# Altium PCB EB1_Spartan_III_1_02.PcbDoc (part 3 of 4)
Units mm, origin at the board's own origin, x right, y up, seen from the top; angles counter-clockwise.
Board outline 165.1 x 115.01 mm, 6 copper layers (Top Layer, MidLayer1, VCC Plane, GND Plane, MidLayer2, Bottom Layer); 356 components, 386 nets, 1788 pads, 779 vias.
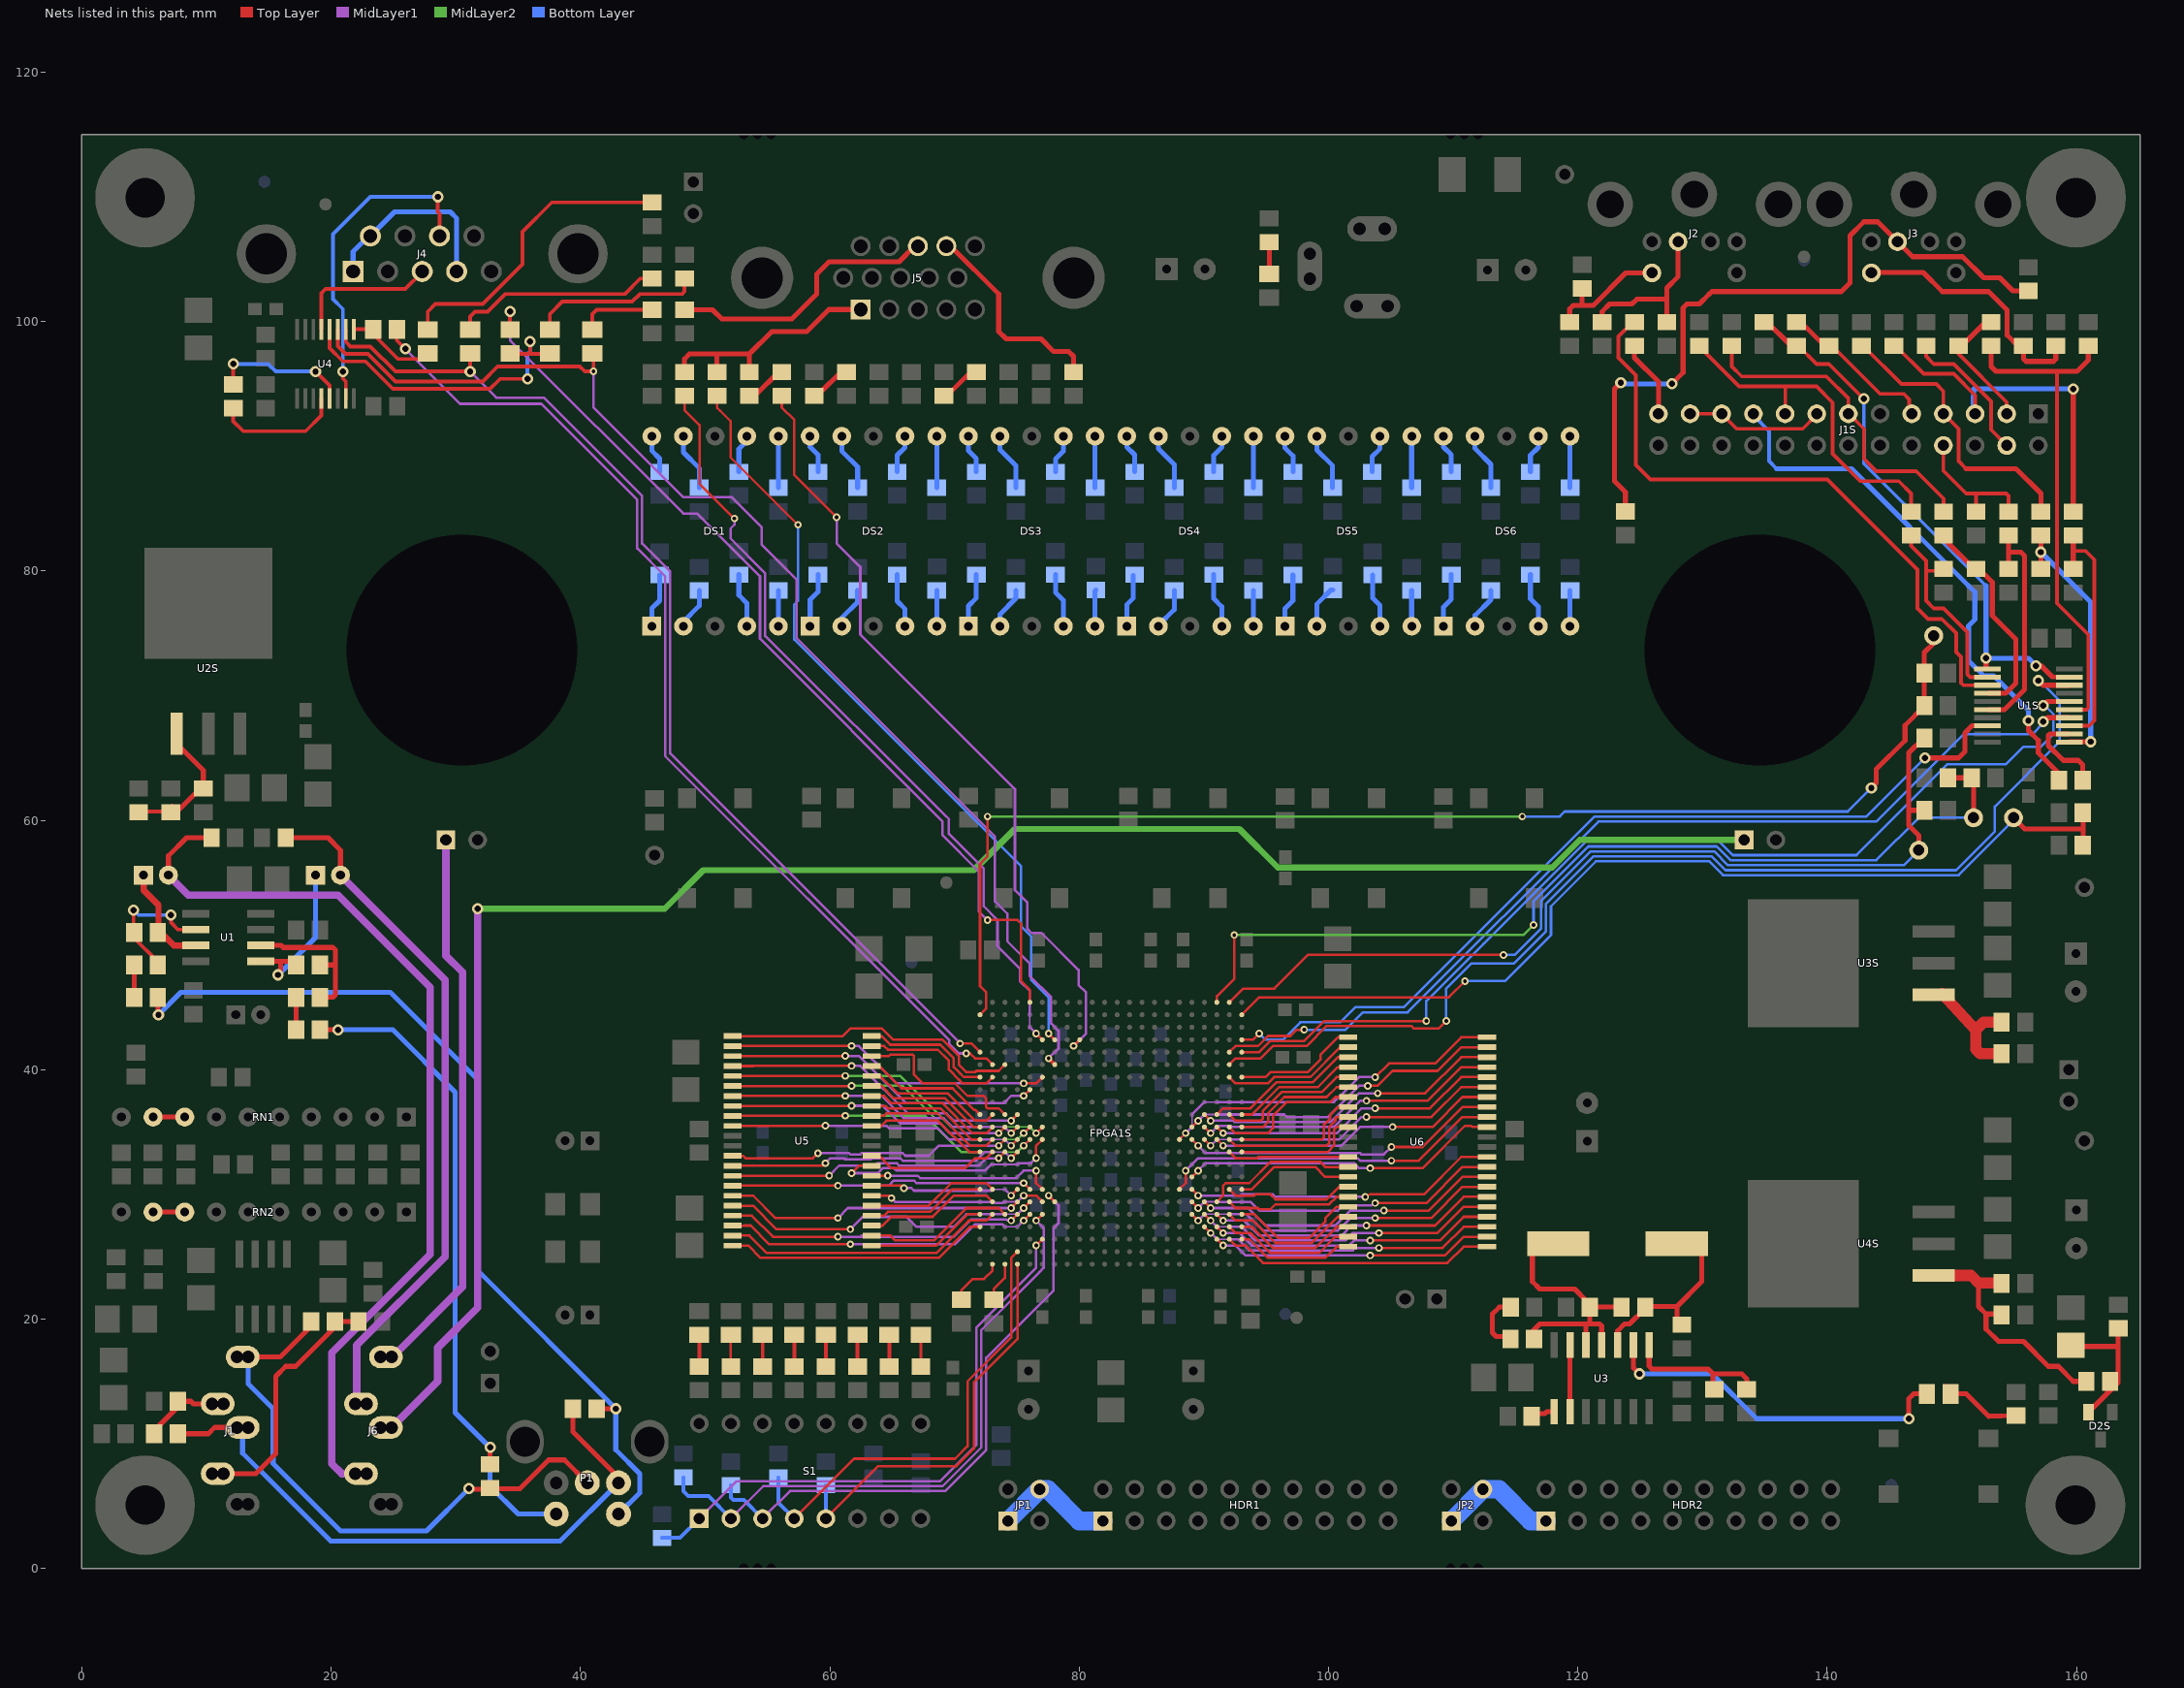
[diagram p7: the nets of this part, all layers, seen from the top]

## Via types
v1: diameter 0.6, hole 0.3, Top Layer to Bottom Layer, tented both sides, 427 vias
v2: diameter 1.6, hole 1, Top Layer to Bottom Layer, 224 vias
v3: diameter 0.9, hole 0.5, Top Layer to Bottom Layer, tented both sides, 126 vias
v4: diameter 1.27, hole 0.711, Top Layer to Bottom Layer, tented both sides, 2 vias

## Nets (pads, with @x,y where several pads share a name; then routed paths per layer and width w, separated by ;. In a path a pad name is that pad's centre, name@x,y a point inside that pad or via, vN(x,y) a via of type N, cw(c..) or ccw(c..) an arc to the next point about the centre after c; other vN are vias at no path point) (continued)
NetC22_1: C22.1 U4.4 | length 10.3
  Top Layer w0.3: C22.1@12.15,93.05 12.15,92 12.95,91.2 17.95,91.2 19.225,92.475 U4.4@19.225,93.825
NetC22_2: C22.2 U4.5 | length 11.1
  Top Layer w0.3: C22.2@12.15,94.95 v3(12.15,96.6) ; v3(18.75,96) 19.875,94.875 U4.5@19.875,93.825
  Bottom Layer w0.3: v3(12.15,96.6) 14.95,96.6 15.55,96 v3(18.75,96)
NetC30_2: C30.2 L1.2 | length 4.9
  Top Layer w0.4: C30.2@114.62,20.955 113.705,20.955 113.15,20.4 113.15,18.9 113.45,18.6 114.6,18.6 L1.2@114.7,18.6
NetC31_1: C31.1 CR1.2 R112.2 U3.3 | length 15.3
  Top Layer w0.4: U3.3@123.19,17.915 123.19,19.04 123.75,19.6 124.15,19.6 R112.2@125.35,20.8 ; R112.2@125.35,21 125.355,21.005 125.41,21.005 127.955,21.005 ; CR1.2@127.94,26.035 129.515,26.035 129.95,25.6 129.95,23 127.955,21.005 ; C31.1@127.95,19.9 127.955,19.905 127.955,21.005
NetC32_2: C32.2 CR1.1 L1.1 R112.1 U3.4 U3.5 | length 23.5
  Top Layer w0.4: L1.1@116.42,18.6 116.42,19.07 116.95,19.6 120.55,19.6 ; CR1.1@118.35,26 116.35,26 116.35,23 116.95,22.4 119.75,22.4 C32.2@120.75,21.4 ; U3.5@120.65,17.915 120.65,19.5 120.55,19.6 ; C32.2@120.95,21 120.95,20.955 120.95,19.6 ; C32.2@120.965,20.955 R112.1@123.51,20.955 ; U3.4@121.92,17.915 121.92,19.43 121.75,19.6 120.95,19.6 ; 120.55,19.6 120.95,19.6
NetC33_1: C33.1 P1.2 R115.2 | length 53.3
  Top Layer w0.4: C33.1@19.1,43.2 v3(20.55,43.2) ; R115.2@32.75,8.3 R115.2@32.75,8.35 v3(32.75,9.7)
  Bottom Layer w0.4: v3(20.55,43.2) 24.95,43.2 29.95,38.2 29.95,12.5 v3(32.75,9.7) 32.75,6.6 34.99,4.36 P1.2@38.05,4.36
NetC33_2: C33.2 R116.1 | length 2.6
  Top Layer w0.4: C33.2@17.2,43.2 R116.1@17.2,45.8
NetC35_1: C35.1 P1.5 R114.2 | length 73.1
  Top Layer w0.4: C35.1@6.1,45.8 6.1,44.45 v3(6.15,44.4) ; R114.2@41.3,12.8 v3(42.85,12.8)
  Bottom Layer w0.4: v3(6.15,44.4) 7.95,46.2 24.75,46.2 31.75,39.2 31.75,23.9 42.84,12.81 42.84,12.8 42.84,9.51 44.75,7.6 44.75,6.06 P1.5@43.05,4.36
NetC35_2: C35.2 R117.1 | length 2.6
  Top Layer w0.4: C35.2@4.2,45.8 R117.1@4.2,48.4
NetC36_1: C36.1 R118.2 U1.1 | length 13.5
  Top Layer w0.4: U1.1@14.35,48.695 15.95,48.695 ; v3(15.75,47.6) 15.95,47.8 15.95,48.695 ; R118.2@17.35,48.6 17.255,48.695 17.2,48.695 15.95,48.695
  Bottom Layer w0.4: v3(15.75,47.6) 18.75,50.6 C36.1@18.75,55.6
NetC36_2: C36.2 J6.4 J6.4A J6.4B R120.2 | length 56.7
  Top Layer w0.4: R120.2@16.35,58.6 19.75,58.6 20.75,57.6 C36.2@20.75,55.6
  MidLayer1 w0.6: C36.2@20.75,55.6 29.15,47.2 29.15,25 22.05,17.9 22.05,13.3 J6.4B@22.15,13.2 ; J6.4B@21.95,13.2 J6.4B@22.15,13.2 ; J6.4A@22.75,13.3 J6.4A@22.65,13.2 ; J6.4A@22.85,13.2 J6.4A@22.65,13.2 ; J6.4B@22.15,13.2 J6.4@22.4,13.2 J6.4A@22.65,13.2
NetC38_1: C38.1 R119.2 U1.7 | length 8.4
  Top Layer w0.5: C38.1@4.95,55.6 4.95,54.4 6.15,53.2 6.15,51.2 6.225,51.125 7.385,49.965 U1.7@9.15,49.965
NetC38_2: C38.2 J6.2 J6.2A J6.2B R121.2 | length 74.9
  Top Layer w0.4: C38.2@6.95,55.6 6.95,57.15 8.4,58.6 R121.2@10.4,58.6
  MidLayer1 w0.6: C38.2@6.95,55.6 8.55,54 20.55,54 27.95,46.6 27.95,25.2 20.05,17.3 20.05,8.4 20.85,7.6 J6.2B@21.95,7.6 J6.2@22.4,7.6 J6.2A@22.85,7.6
NetC79S_2: C79S.2 D2S.2 R30S.1 R38S.2 | length 12.1
  Top Layer w0.4: C79S.2@159.95,17.8 163.35,17.8 ; D2S.2@160.975,12.53 163.073,14.627 163.35,14.905 163.35,15 163.35,17.8 ; R30S.1@163.35,19.25 163.35,17.8
  Top Layer w0.5: 162.55,14.2 163.025,14.675 163.05,14.7 R38S.2@163.05,15
NetDS1_1: DS1.1 R41.1 | length 4.4
  Bottom Layer w0.4: DS1.1@45.72,75.565 45.72,76.99 46.35,77.62 R41.1@46.35,79.67
NetDS1_2: DS1.2 R37.1 | length 3.4
  Bottom Layer w0.4: DS1.2@48.26,75.565 48.26,75.93 49.53,77.2 R37.1@49.53,78.425
NetDS1_4: DS1.4 R33.1 | length 4.4
  Bottom Layer w0.4: R33.1@52.705,79.695 52.705,78.065 53.34,77.43 DS1.4@53.34,75.565
NetDS1_5: DS1.5 R53.1 | length 2.9
  Bottom Layer w0.4: DS1.5@55.88,75.565 R53.1@55.88,78.425
NetDS1_6: DS1.6 R29.1 | length 4.1
  Bottom Layer w0.4: R29.1@55.88,86.675 DS1.6@55.88,90.805
NetDS1_7: DS1.7 R25.1 | length 3.1
  Bottom Layer w0.4: R25.1@52.705,87.945 52.705,89.775 53.34,90.41 DS1.7@53.34,90.805
NetDS1_9: DS1.9 R45.1 | length 4.7
  Bottom Layer w0.4: DS1.9@48.26,90.805 48.26,89.51 49.53,88.24 R45.1@49.53,86.675
NetDS1_10: DS1.10 R49.1 | length 3.1
  Bottom Layer w0.4: DS1.10@45.72,90.805 45.72,89.65 46.355,89.015 R49.1@46.355,87.945
NetDS2_1: DS2.1 R42.1 | length 4.4
  Bottom Layer w0.4: DS2.1@58.42,75.565 58.42,77.69 59.055,78.325 R42.1@59.055,79.695
NetDS2_2: DS2.2 R38.1 | length 3.4
  Bottom Layer w0.4: DS2.2@60.96,75.565 60.96,76.23 62.23,77.5 R38.1@62.23,78.425
NetDS2_4: DS2.4 R34.1 | length 4.4
  Bottom Layer w0.4: R34.1@65.405,79.695 65.405,77.565 66.04,76.93 DS2.4@66.04,75.565
NetDS2_5: DS2.5 R54.1 | length 2.9
  Bottom Layer w0.4: DS2.5@68.58,75.565 R54.1@68.58,78.425
NetDS2_6: DS2.6 R30.1 | length 4.1
  Bottom Layer w0.4: R30.1@68.58,86.675 DS2.6@68.58,90.805
NetDS2_7: DS2.7 R26.1 | length 3.1
  Bottom Layer w0.4: R26.1@65.405,87.945 65.405,89.275 66.04,89.91 DS2.7@66.04,90.805
NetDS2_9: DS2.9 R46.1 | length 4.7
  Bottom Layer w0.4: DS2.9@60.96,90.805 60.96,89.61 62.23,88.34 R46.1@62.23,86.675
NetDS2_10: DS2.10 R50.1 | length 3.1
  Bottom Layer w0.4: DS2.10@58.42,90.805 58.42,89.95 59.055,89.315 R50.1@59.055,87.945
NetDS3_1: DS3.1 R43.1 | length 4.4
  Bottom Layer w0.4: DS3.1@71.12,75.565 71.12,77.19 71.755,77.825 R43.1@71.755,79.695
NetDS3_2: DS3.2 R39.1 | length 3.4
  Bottom Layer w0.4: DS3.2@73.66,75.565 73.66,76.53 74.93,77.8 R39.1@74.93,78.425
NetDS3_4: DS3.4 R35.1 | length 4.4
  Bottom Layer w0.4: R35.1@78.105,79.695 78.105,78.265 78.74,77.63 DS3.4@78.74,75.565
NetDS3_5: DS3.5 R55.1 | length 2.9
  Bottom Layer w0.4: DS3.5@81.28,75.565 81.28,78.4 R55.1@81.35,78.47
NetDS3_6: DS3.6 R31.1 | length 4.1
  Bottom Layer w0.4: R31.1@81.28,86.675 DS3.6@81.28,90.805
NetDS3_7: DS3.7 R27.1 | length 3.1
  Bottom Layer w0.4: R27.1@78.105,87.945 78.105,88.975 78.74,89.61 DS3.7@78.74,90.805
NetDS3_9: DS3.9 R47.1 | length 4.7
  Bottom Layer w0.4: DS3.9@73.66,90.805 73.66,89.71 74.93,88.44 R47.1@74.93,86.675
NetDS3_10: DS3.10 R51.1 | length 3.1
  Bottom Layer w0.4: DS3.10@71.12,90.805 71.12,89.65 71.755,89.015 R51.1@71.755,87.945
NetDS4_1: DS4.1 R44.1 | length 4.3
  Bottom Layer w0.4: DS4.1@83.82,75.565 83.82,77.29 84.35,77.82 R44.1@84.35,79.62
NetDS4_2: DS4.2 R40.1 | length 3.4
  Bottom Layer w0.4: DS4.2@86.36,75.565 86.36,75.63 87.63,76.9 R40.1@87.63,78.425
NetDS4_4: DS4.4 R36.1 | length 4.4
  Bottom Layer w0.4: R36.1@90.805,79.695 90.805,77.765 91.44,77.13 DS4.4@91.44,75.565
NetDS4_5: DS4.5 R56.1 | length 2.9
  Bottom Layer w0.4: DS4.5@93.98,75.565 R56.1@93.98,78.425
NetDS4_6: DS4.6 R32.1 | length 4.1
  Bottom Layer w0.4: R32.1@93.98,86.675 DS4.6@93.98,90.805
NetDS4_7: DS4.7 R28.1 | length 3.1
  Bottom Layer w0.4: R28.1@90.805,87.945 90.805,89.275 91.44,89.91 DS4.7@91.44,90.805
NetDS4_9: DS4.9 R48.1 | length 4.7
  Bottom Layer w0.4: DS4.9@86.36,90.805 86.36,89.81 87.63,88.54 R48.1@87.63,86.675
NetDS4_10: DS4.10 R52.1 | length 3.1
  Bottom Layer w0.4: DS4.10@83.82,90.805 83.82,89.95 84.455,89.315 R52.1@84.455,87.945
NetDS5_1: DS5.1 R65.1 | length 4.4
  Bottom Layer w0.4: DS5.1@96.52,75.565 96.52,76.99 97.15,77.62 R65.1@97.15,79.67
NetDS5_2: DS5.2 R63.1 | length 3.5
  Bottom Layer w0.4: DS5.2@99.06,75.565 99.06,77.33 100.2,78.47 R63.1@100.35,78.47
NetDS5_4: DS5.4 R61.1 | length 4.4
  Bottom Layer w0.4: R61.1@103.54,79.675 103.54,77.83 104.14,77.23 DS5.4@104.14,75.565
NetDS5_5: DS5.5 R71.1 | length 2.9
  Bottom Layer w0.4: DS5.5@106.68,75.565 R71.1@106.68,78.425
NetDS5_6: DS5.6 R59.1 | length 4.1
  Bottom Layer w0.4: R59.1@106.68,86.675 DS5.6@106.68,90.805
NetDS5_7: DS5.7 R57.1 | length 3.1
  Bottom Layer w0.4: R57.1@103.505,87.945 103.505,89.175 104.14,89.81 DS5.7@104.14,90.805
NetDS5_9: DS5.9 R67.1 | length 4.7
  Bottom Layer w0.4: DS5.9@99.06,90.805 99.06,89.71 100.33,88.44 R67.1@100.33,86.675
NetDS5_10: DS5.10 R69.1 | length 3.1
  Bottom Layer w0.4: DS5.10@96.52,90.805 96.52,89.85 97.155,89.215 R69.1@97.155,87.945
NetDS6_1: DS6.1 R66.1 | length 4.4
  Bottom Layer w0.4: DS6.1@109.22,75.565 109.22,77.09 109.855,77.725 R66.1@109.855,79.695
NetDS6_2: DS6.2 R64.1 | length 3.4
  Bottom Layer w0.4: DS6.2@111.76,75.565 111.76,76.43 113.03,77.7 R64.1@113.03,78.425
NetDS6_4: DS6.4 R62.1 | length 4.4
  Bottom Layer w0.4: R62.1@116.205,79.695 116.205,77.765 116.84,77.13 DS6.4@116.84,75.565
NetDS6_5: DS6.5 R72.1 | length 2.9
  Bottom Layer w0.4: DS6.5@119.38,75.565 R72.1@119.38,78.425
NetDS6_6: DS6.6 R60.1 | length 4.1
  Bottom Layer w0.4: R60.1@119.38,86.675 DS6.6@119.38,90.805
NetDS6_7: DS6.7 R58.1 | length 3.1
  Bottom Layer w0.4: R58.1@116.205,87.945 116.205,89.275 116.84,89.91 DS6.7@116.84,90.805
NetDS6_9: DS6.9 R68.1 | length 4.7
  Bottom Layer w0.4: DS6.9@111.76,90.805 111.76,89.81 113.03,88.54 R68.1@113.03,86.675
NetDS6_10: DS6.10 R70.1 | length 3.1
  Bottom Layer w0.4: DS6.10@109.22,90.805 109.22,89.95 109.855,89.315 R70.1@109.855,87.945
NetFPGA1S_A20: FPGA1S.A20 R8S.2 R12S.2 TP4S.1 | length 76.4
  Top Layer w0.2: FPGA1S.A20@91.05,45.4 91.05,45.9 92.45,47.3 v1(92.45,50.8)
  Top Layer w0.4: R8S.2@149.7,63.4 R12S.2@151.6,63.4 151.75,63.25 TP4S.1@151.75,60.2
  MidLayer2 w0.2: v1(92.45,50.8) 115.65,50.8 v1(116.45,51.6)
  Bottom Layer w0.2: v1(116.45,51.6) 116.45,53.5 120.85,57.9 131.15,57.9 132.25,56.8 143.95,56.8 147.35,60.2 TP4S.1@151.75,60.2
NetFPGA1S_A21: FPGA1S.A21 R7S.2 R11S.2 TP3S.1 | length 73.7
  Top Layer w0.2: FPGA1S.A21@92.05,45.4 93.15,46.5 95.65,46.5 98.35,49.2 v1(114.05,49.2)
  Top Layer w0.4: TP3S.1@147.35,57.6 147.35,58.8 146.55,59.6 146.55,60.8 ; R7S.2@147.8,60.8 146.55,60.8 ; R11S.2@147.8,66.6 147.75,66.6 146.55,65.4 146.55,60.8
  Bottom Layer w0.2: v1(114.05,49.2) 114.95,49.2 117.05,51.3 117.05,53.5 121.05,57.5 130.95,57.5 132.05,56.4 146.15,56.4 TP3S.1@147.35,57.6
NetFPGA1S_AB2: FPGA1S.AB2 R3S.2 | length 4.5
  Top Layer w0.2: R3S.2@70.55,21.4 R3S.2@70.625,21.475 ; R3S.2@70.55,21.55 70.55,22.3 71.462,23.212 72.362,23.212 73.05,23.9 FPGA1S.AB2@73.05,24.4
NetFPGA1S_AB3: FPGA1S.AB3 R4S.2 | length 3.2
  Top Layer w0.2: R4S.2@73.15,21.55 73.15,22.4 74.05,23.3 FPGA1S.AB3@74.05,24.4
NetFPGA1S_B1: FPGA1S.B1 R5S.2 R9S.2 TP1S.1 | length 103
  Top Layer w0.2: FPGA1S.B1@72.05,44.4 72.55,44.9 72.55,46.2 72.05,46.7 72.05,56.5 72.65,57.1 v1(72.65,60.3)
  Top Layer w0.4: v3(143.55,62.6) 143.95,63 143.95,64.1 146.25,66.4 146.25,67.6 R9S.2@147.8,69.15 ; R9S.2@147.8,68.85 R9S.2@147.8,69.15 ; TP1S.1@148.55,74.8 148.55,74.2 147.8,73.45 R5S.2@147.8,71.8 R9S.2@147.8,69.2 R9S.2@147.8,69.15
  MidLayer2 w0.2: v1(72.65,60.3) v1(115.55,60.3)
  Bottom Layer w0.2: v1(115.55,60.3) 118.55,60.3 118.95,60.7 141.65,60.7 v3(143.55,62.6)
NetFPGA1S_B22: FPGA1S.B22 R6S.2 R10S.2 TP2S.1 | length 79.4
  Top Layer w0.2: FPGA1S.B22@93.05,44.4 94.45,45.8 109.65,45.8 v1(110.95,47.1)
  Top Layer w0.4: TP2S.1@154.95,60.2 155.85,59.3 160.55,59.3 ; R10S.2@160.5,58 160.55,58.05 160.55,59.3 ; R6S.2@160.55,60.6 160.55,59.3
  Bottom Layer w0.2: v1(110.95,47.1) 114.15,47.1 117.85,50.8 117.85,53.1 121.45,56.7 130.55,56.7 131.65,55.6 150.55,55.6 154.95,60 TP2S.1@154.95,60.2
NetJ1_2: J1.2 J1.2A J1.2B R3.2 R113.1 | length 19.8
  Top Layer w0.4: J1.2A@11.35,7.6 13.95,7.6 15.55,9.2 15.55,15.4 16.35,16.2 17.15,16.2 20.3,19.35 R113.1@20.3,19.8 R3.2@22.2,19.8
NetJ1_4: J1.4 J1.4A J1.4B R1.1 R2.2 | length 6.7
  Top Layer w0.4: R1.1@5.95,11.2 7.7,12.95 R2.2@7.7,13.4 8.75,13.4 8.95,13.2 J1.4B@10.45,13.2 J1.4@10.9,13.2 J1.4A@11.35,13.2
NetJ1S_2: J1S.2 R14S.2 R28S.2 | length 10
  Top Layer w0.3: R14S.2@150.55,98.05 150.55,97.4 154.41,93.54 J1S.2@154.41,92.6
  Top Layer w0.4: R14S.2@150.495,98.05 150.495,98.11 150.55,98.11 150.86,98.11 R28S.2@152.65,99.9
NetJ1S_3: J1S.3 R15S.2 R27S.2 | length 29.5
  Top Layer w0.3: R15S.2@145.35,98.05 145.5,98.05 147.75,95.8 150.15,95.8 151.87,94.08 J1S.3@151.87,92.6
  Top Layer w0.4: R27S.2@159.75,84.75 v3(159.75,94.6)
  Bottom Layer w0.4: J1S.3@151.67,92.6 151.67,92.608 151.75,94.6 v3(159.75,94.6)
NetJ1S_4: J1S.4 R16S.2 R26S.2 | length 23.4
  Top Layer w0.3: R16S.2@142.75,98.05 142.9,98.05 145.95,95 148.75,95 149.33,94.42 J1S.4@149.33,92.6 149.35,92.6 150.55,91.4 150.55,88.8 151.15,88.2 ; J1S.4@149.13,92.6 J1S.4@149.15,92.6
  Top Layer w0.4: 151.15,88.2 155.15,88.2 157.15,86.2 R26S.2@157.15,84.75
NetJ1S_5: J1S.5 R17S.2 R25S.2 | length 12.8
  Top Layer w0.3: R17S.2@140.15,98.05 140.4,98.05 144.25,94.2 146.15,94.2 146.59,93.76 J1S.5@146.59,92.6
  Top Layer w0.4: R25S.2@137.55,99.95 137.9,99.95 139.8,98.05 R17S.2@140.15,98.05
NetJ1S_7: J1S.7 R18S.2 R24S.2 | length 26.4
  Top Layer w0.3: R18S.2@132.35,98.05 132.35,96.4 133.15,95.6 139.95,95.6 141.71,93.84 J1S.7@141.71,92.6 141.75,92.6 142.95,91.4 142.95,89 143.95,88 147.15,88 149.35,85.8 R24S.2@149.35,84.75
  Top Layer w0.4: R24S.2@149.35,84.6 R24S.2@149.35,84.75
NetJ1S_8: J1S.8 J1S.11 J1S.12 | length 11.4
  Top Layer w0.3: J1S.12@129.01,92.6 131.35,92.6 J1S.11@131.55,92.6 132.75,91.4 138.05,91.4 139.17,92.52 J1S.8@139.17,92.6
  Top Layer w0.4: J1S.12@128.812,92.664 J1S.12@129.011,92.659
NetJ1S_9: J1S.9 R19S.2 R23S.2 | length 28.1
  Top Layer w0.3: R19S.2@129.75,98.05 129.75,98 132.95,94.8 136.65,94.8 ; J1S.9@136.63,92.6 136.63,92.62 136.65,92.64 136.65,94.8 ; R23S.2@146.75,84.75 146.75,86.2 145.75,87.2 142.65,87.2 140.45,89.4 140.45,93.5 139.15,94.8 136.65,94.8
  Top Layer w0.4: R19S.2@129.75,98.05 R19S.2@129.75,98.2
NetJ1S_10: J1S.10 R22S.2 | length 43.9
  Top Layer w0.4: v3(156.15,68) 156.15,67.2 156.95,66.4 156.95,65.4 158.6,63.75 R22S.2@158.6,63.2
  Bottom Layer w0.3: J1S.10@134.09,92.6 134.09,92.46 135.35,91.2 135.35,88.8 135.95,88.2
  Bottom Layer w0.4: 135.95,88.2 141.95,88.2 151.35,78.8 151.85,78.3 151.85,76.1 151.35,75.6 151.35,72.8 152.55,71.6 153.35,71.6 156.15,68.8 v3(156.15,68)
NetJ1S_13: J1S.13 R21S.2 | length 6.4
  Top Layer w0.4: R21S.2@124.46,97.91 R21S.2@124.55,98 ; R21S.2@124.55,98.05 R21S.2@124.55,98 ; J1S.13@126.47,92.6 126.47,95.18 124.55,97.1 R21S.2@124.55,98
NetJ1S_15: J1S.15 R20S.2 | length 11.6
  Top Layer w0.3: R20S.2@147.95,98.05 147.95,97.2 148.55,96.6 150.15,96.6 153.15,93.6 153.15,91.32 J1S.15@154.41,90.06
NetJ1S_17: J1S.17 R13S.2 R29S.2 | length 10.8
  Top Layer w0.3: J1S.17@149.33,90.06 149.33,88.02 151.15,86.2 151.95,86.2 ; R13S.2@151.95,84.75 151.95,86.2 ; R29S.2@154.55,84.75 154.55,86 154.35,86.2 151.95,86.2
NetJ2_1: J2.1 R87.2 R88.2 | length 13.3
  Top Layer w0.4: R88.2@121.95,99.95 121.95,100.8 122.55,101.4 124.35,101.4 124.75,101.8 127.15,101.8 ; R87.2@127.15,99.95 127.15,101.8 ; J2.1@128.05,106.4 128.05,103.6 127.15,102.7 127.15,101.8
NetJ2_6: J2.6 R86.2 R89.2 | length 10.2
  Top Layer w0.4: R89.2@119.35,99.95 119.35,101 119.65,101.3 120.35,101.3 ; R86.2@120.35,102.65 120.35,101.3 ; J2.6@125.95,103.9 123.85,103.9 121.25,101.3 120.35,101.3
NetJ3_1: J3.1 R85.2 R92.2 | length 56.6
  Top Layer w0.4: v3(123.45,95.1) 122.95,94.6 122.95,87.2 123.825,86.325 R92.2@123.825,84.77 ; v3(127.55,95) 128.45,95.9 128.45,101.1 128.75,101.4 129.75,101.4 130.55,102.2 130.75,102.4 141.15,102.4 141.85,103.1 141.85,106.9 142.95,108 144.05,108 J3.1@145.65,106.4 146.85,105.2 150.87,105.2 152.57,103.5 153.85,103.5 154.9,102.45 R85.2@156.15,102.45
  Bottom Layer w0.4: v3(123.45,95.1) 123.55,95 v3(127.55,95)
NetJ3_6: J3.6 R84.2 R93.2 | length 20.2
  Top Layer w0.4: J3.6@144.07,103.935 147.715,103.935 149.25,102.4 152.95,102.4 154.45,100.9 154.45,98.9 155.3,98.05 R84.2@155.75,98.05 155.75,97 155.95,96.8 158.15,96.8 158.35,97 R93.2@158.35,98.05
NetJ4_1: J4.1 J4.4 J4.6 | length 15.7
  Bottom Layer w0.4: J4.1@21.765,104.015 21.765,105.615 23.005,106.855 J4.6@23.15,106.855 25.095,108.8 29.55,108.8 30.075,108.275 J4.4@30.075,104.015
NetJ5_13: J5.13 R94.2 | length 22.4
  Top Layer w0.4: R94.2@48.35,100.95 50.6,100.95 51.35,100.2 56.95,100.2 58.95,102.2 58.95,103.8 59.95,104.8 65.55,104.8 66.836,106.086 67.064,106.086 J5.13@67.064,106.045
NetJ5_14: J5.14 R95.2 | length 16.9
  Top Layer w0.4: J5.14@69.354,106.045 69.705,106.045 73.55,102.2 73.55,99.2 74.15,98.6 76.95,98.6 77.95,97.6 79.15,97.6 79.55,97.2 R95.2@79.55,95.95
NetLD0_2: LD0.2 R74.2 | length 2.5
  Top Layer w0.3: R74.2@49.53,16.19 LD0.2@49.53,18.735
NetLD1_2: LD1.2 R75.2 | length 2.6
  Top Layer w0.2: R75.2@52.05,16.1 52.05,16.19 LD1.2@52.05,18.7
NetLD2_2: LD2.2 R76.2 | length 2.5
  Top Layer w0.3: R76.2@54.61,16.19 LD2.2@54.61,18.735
NetLD3_2: LD3.2 R77.2 | length 2.5
  Top Layer w0.3: R77.2@57.15,16.19 LD3.2@57.15,18.735
NetLD4_2: LD4.2 R78.2 | length 2.5
  Top Layer w0.3: R78.2@59.69,16.19 LD4.2@59.69,18.735
NetLD5_2: LD5.2 R79.2 | length 2.5
  Top Layer w0.3: R79.2@62.23,16.19 LD5.2@62.23,18.735
NetLD6_2: LD6.2 R80.2 | length 2.5
  Top Layer w0.3: R80.2@64.77,16.19 LD6.2@64.77,18.735
NetLD7_2: LD7.2 R81.2 | length 2.5
  Top Layer w0.2: R81.2@67.31,16.19 LD7.2@67.31,18.735
NetLED1_2: LED1.2 R83.2 | length 2.5
  Top Layer w0.4: LED1.2@95.25,103.82 R83.2@95.25,106.365
NetLED2_1: LED2.1 R73.1 | length 6.7
  Top Layer w0.4: LED2.1@149.55,14.6 LED2.1@150.025,14.125 ; LED2.1@149.9,14 151.15,14 152.95,12.2 R73.1@155.15,12.25
NetLED2_2: LED2.2 U3.2 | length 28.8
  Top Layer w0.4: U3.2@124.46,17.915 124.46,16.09 v3(124.95,15.6) ; v3(146.55,12) 146.55,13.6 146.95,14 LED2.2@148,14
  Bottom Layer w0.4: v3(124.95,15.6) 130.75,15.6 134.35,12 v3(146.55,12)
NetLED4_1: LED4.1 R96.1 | length 6.2
  Top Layer w0.3: LED4.1@40.95,99.35 40.95,100.6 41.3,100.95 R96.1@45.75,100.95
NetLED5_1: LED5.1 R97.1 | length 16.9
  Top Layer w0.3: LED5.1@31.15,99.35 31.15,100.4 31.55,100.8 32.55,100.8 33.95,102.2 43.55,102.2 44.8,103.45 R97.1@45.75,103.45
NetLED6_1: LED6.1 R98.1 | length 13.8
  Top Layer w0.3: LED6.1@37.55,99.35 37.55,100.6 38.55,101.6 44.15,101.6 44.75,102.2 48.15,102.2 48.35,102.4 R98.1@48.35,103.45
NetLED6_2: LED6.2 R90.2 U4.12 | length 25.7
  Top Layer w0.3: U4.12@19.875,99.375 19.875,97.875 20.95,96.8 22.75,96.8 24.95,94.6 32.75,94.6 33.55,95.4 v3(35.75,95.4) ; R90.2@34.75,97.4 35.95,97.4 ; v3(35.95,98.4) 35.95,97.4 ; LED6.2@37.35,97.4 35.95,97.4
  Bottom Layer w0.3: v3(35.75,95.4) 35.75,97.4 35.95,97.6 v3(35.95,98.4)
NetLED7_1: LED7.1 R99.1 | length 24.6
  Top Layer w0.3: LED7.1@27.75,99.35 27.75,100.8 28.35,101.4 32.15,101.4 35.35,104.6 35.35,107.2 37.7,109.55 R99.1@45.75,109.55
NetLED7_2: LED7.2 R91.2 U4.9 | length 7.3
  Top Layer w0.3: U4.9@21.825,99.375 R91.2@23.375,99.375 23.375,98.975 25.35,97 27.75,97 LED7.2@27.95,97
NetR24_2: R24.2 R82.2 U3.1 | length 11.8
  Top Layer w0.4: U3.1@125.73,17.915 125.73,16.22 125.95,16 130.45,16 130.85,15.6 ; R82.2@130.85,14.6 130.85,15.6 ; R24.2@133.55,14.35 133.55,15.2 133.15,15.6 130.85,15.6
NetR31S_2: R31S.2 R37S.1 R38S.1 U4S.1 | length 20
  Top Layer w0.4: 152.15,22.9 152.15,21 152.75,20.4 ; R31S.2@153.99,20.32 153.91,20.4 152.75,20.4 ; R38S.1@160.8,15 159.75,15 158.55,16.2 157.75,16.2 155.75,18.2 153.75,18.2 152.75,19.2 152.75,20.4
  Top Layer w0.9: U4S.1@149.225,23.495 151.555,23.495 152.15,22.9 153.95,22.9 R37S.1@153.99,22.86
NetR32S_1: R32S.1 R35S.2 R36S.2 U2S.1 | length 11.1
  Top Layer w0.3: R35S.2@4.55,60.7 7.15,60.7 R36S.2@7.275,60.825
  Top Layer w0.4: R36S.2@7.15,61 7.175,61.025 7.275,61.125 R36S.2@7.225,61.075 ; R36S.2@7.275,60.825 R36S.2@7.325,60.875 ; R36S.2@7.325,60.375 7.375,60.425 R32S.1@9.25,62.3 ; U2S.1@7.61,66.95 7.61,66.14 9.75,64 9.75,63.15 R32S.1@9.75,62.55
NetR33S_1: R33S.1 R34S.2 U3S.1 | length 10
  Top Layer w0.9: U3S.1@149.25,46.1 151.93,43.18 ; R34S.2@153.99,41.275 152.275,41.275 151.93,41.62 151.93,43.18 ; R33S.1@153.99,43.815 152.565,43.815 151.93,43.18
NetR100_2: R100.2 R101.1 | length 3.2
  Top Layer w0.3: R101.1@53.55,94.05 R101.1@54,94.05
  Top Layer w0.4: R101.1@54,94.05 R100.2@55.95,96
NetR103_2: R103.2 R104.1 | length 3.3
  Top Layer w0.4: R104.1@58.75,94.05 59,94.05 61.125,96.175 R103.2@61.15,96.2
NetR106_2: R106.2 R107.1 | length 3.6
  Top Layer w0.4: R107.1@68.95,94 69.15,94 69.35,94 71.3,95.95 R106.2@71.75,95.95
NetR116_2: R116.2 R118.1 U1.2 | length 12.3
  Top Layer w0.4: U1.2@14.35,49.965 15.985,49.965 16.15,49.8 20.15,49.8 20.35,49.6 20.35,48.4 ; R116.2@19.1,45.8 20.15,45.8 20.35,46 20.35,48.4 ; R118.1@19.1,48.4 20.35,48.4
NetR117_2: R117.2 R119.1 U1.6 | length 11
  Top Layer w0.3: v3(4.15,52.8) 4.15,51 4.15,50.6 R117.2@6.15,48.6 ; v3(7.15,52.4) 7.15,51.8 7.715,51.235 U1.6@9.15,51.235
  Bottom Layer w0.3: v3(4.15,52.8) 4.55,52.4 v3(7.15,52.4)
NetR122_2: R122.2 U3.8 | length 1.9
  Top Layer w0.4: R122.2@116.3,12.4 117.35,12.4 117.515,12.565 U3.8@118.11,12.565
NetRN1_8: RN1.8 RN1.9 | length 2.5
  Top Layer w0.4: RN1.9@5.715,36.195 RN1.8@8.255,36.195
NetRN2_8: RN2.8 RN2.9 | length 2.5
  Top Layer w0.4: RN2.9@5.715,28.575 RN2.8@8.255,28.575
NetU3_6: U3.6 U3.9 | length 5.4
  Top Layer w0.4: U3.9@119.38,12.565 U3.6@119.38,17.915
POT_IN_L: J1.5 J1.5A J1.5B P1.1 R113.2 R115.1 | length 46.4
  Top Layer w0.4: J1.5A@13.35,16.95 15.9,16.95 18.35,19.4 R113.2@18.35,19.8 ; v3(31.05,6.4) 31.1,6.35 32.75,6.35 32.8,6.4 35.15,6.4 37.45,8.7 38.71,8.7 P1.1@40.55,6.86
  Bottom Layer w0.4: J1.5A@13.35,16.95 13.35,14.8 15.35,12.8 15.35,8.4 20.75,3 27.65,3 v3(31.05,6.4)
POT_IN_R: J1.3 J1.3A J1.3B P1.4 R1.2 R114.1 | length 49.9
  Top Layer w0.4: R1.2@7.7,10.8 10.15,10.8 10.65,11.3 J1.3B@12.45,11.3 J1.3@12.9,11.3 ; R114.1@39.4,12.8 39.4,10.95 43.05,7.3 P1.4@43.05,6.86
  Bottom Layer w0.4: J1.3@12.9,11.3 12.9,9.25 15.241,6.909 19.95,2.2 38.39,2.2 P1.4@43.05,6.86
PP_CTRL: C65S.1 R25S.1 U1S.1 U1S.19 | length 43.3
  Top Layer w0.3: R25S.1@137.55,98.05 137.7,98.05 139.15,96.6 140.15,96.6 v3(142.95,93.8)
  Top Layer w0.4: C65S.1@135.05,100.1 135.075,100.075 137.05,98.1 R25S.1@137.45,98.1 ; U1S.1@152.75,72.2 v3(152.75,73) ; v3(156.75,72.4) 157.15,72.4 158.05,71.5 U1S.19@159.425,71.475
  Bottom Layer w0.3: v3(142.95,93.8) 142.95,88.6 152.75,78.8
  Bottom Layer w0.4: 152.75,78.8 v3(152.75,73) 156.15,73 v3(156.75,72.4)
PP_HARD_TCK: C63S.1 R27S.1 U1S.13 | length 19.7
  Top Layer w0.3: U1S.13@159.425,67.575 161.025,67.575 161.45,68 161.45,80.9 160.75,81.6 159.75,81.6
  Top Layer w0.4: C63S.1@159.75,80.15 159.75,81.6 R27S.1@159.75,82.8
PP_HARD_TDI: C62S.1 R28S.1 U1S.15 | length 40.8
  Top Layer w0.3: 158.45,96 158.45,77.4 160.95,74.9 160.95,69 160.825,68.875 U1S.15@159.425,68.875
  Top Layer w0.4: R28S.1@153.15,98.05 153.15,96.4 153.55,96 158.45,96 160.05,96 160.95,96.9 C62S.1@160.95,98.05
PP_HARD_TDO: R21S.1 U1S.3 | length 52.1
  Top Layer w0.3: R21S.1@124.55,99.95 124.4,99.95 123.25,98.8 123.25,97.1 124.65,95.7 124.65,88.5 125.827,87.323 140.027,87.323 147.25,80.1 147.25,77 148.113,76.137 149.213,76.137 150.35,75 150.35,73.5 150.75,73.1 150.75,71 150.925,70.825 U1S.3@152.875,70.825
PP_HARD_TMS: C64S.1 R26S.1 U1S.11 | length 21.2
  Top Layer w0.4: C64S.1@157.15,80.15 v3(157.15,81.5) R26S.1@157.15,82.8 ; U1S.11@159.425,66.275 159.45,66.3 v3(161.15,66.3)
  Bottom Layer w0.4: v3(157.15,81.5) 161.15,77.5 v3(161.15,66.3)
PP_SOFT_TCK: C67S.1 R23S.1 U1S.2 | length 16.6
  Top Layer w0.3: R23S.1@146.75,82.85 146.75,82 147.95,80.8 147.95,80 ; C67S.1@148.95,80 147.95,80 ; U1S.2@152.875,71.475 151.475,71.475 151.25,71.7 151.25,75.1 149.35,77 148.55,77 147.95,77.6 147.95,80
  Top Layer w0.4: R23S.1@146.75,82.75 R23S.1@146.75,82.85 ; C67S.1@149.35,80.15 C67S.1@149.6,80.15
PP_SOFT_TDI: C66S.1 R24S.1 U1S.4 | length 17
  Top Layer w0.4: R24S.1@149.35,82.85 149.35,82.6 151.875,80.075 C66S.1@151.95,80 ; C66S.1@152.15,80.2 153.25,79.1 153.25,76.4 155.15,74.5 155.15,71 154.65,70.5 154.325,70.175 U1S.4@152.875,70.175
PP_SOFT_TDO: R22S.1 U1S.12 | length 7.2
  Top Layer w0.4: U1S.12@159.425,66.925 157.875,66.925 157.75,66.8 157.75,66 158.95,64.8 160.15,64.8 160.5,64.45 R22S.1@160.5,63.2
PP_SOFT_TMS: C61S.1 R29S.1 U1S.6 | length 18.5
  Top Layer w0.4: U1S.6@152.875,68.875 154.225,68.875 155.85,70.5 155.85,81.2 155.55,81.5 154.55,81.5 ; C61S.1@154.55,80.15 154.55,81.5 ; R29S.1@154.55,82.85 154.55,81.5
PWR_USER_1: HDR1.1 JP1.1 JP1.4 | length 9.7
  Bottom Layer w1.5: JP1.1@74.295,3.81 JP1.4@76.835,6.35 77.47,6.35 80.01,3.81 HDR1.1@81.915,3.81
PWR_USER_2: HDR2.1 JP2.1 JP2.4 | length 9.7
  Bottom Layer w1.5: JP2.1@109.855,3.81 JP2.4@112.395,6.35 113.665,6.35 116.205,3.81 HDR2.1@117.44,3.81 HDR2.1@117.475,3.81
RED0: FPGA1S.D9 R100.1 | length 63.8
  Top Layer w0.2: R100.1@56.15,94.05 56.15,93.1 57.15,92.1 57.15,87.7 v1(60.55,84.3) ; v1(79.55,41.9) FPGA1S.D9@80.05,42.4
  MidLayer1 w0.2: v1(60.55,84.3) 60.55,82.2 62.45,80.3 62.45,74.9 74.85,62.5 74.85,54.4 75.85,53.4 75.85,51.3 76.187,50.963 76.987,50.963 79.95,48 79.95,46.8 80.55,46.2 80.55,42.9 v1(79.55,41.9)
RED1: FPGA1S.D7 R102.1 | length 63.1
  Top Layer w0.2: R102.1@50.95,94.05 50.95,93.1 51.216,92.834 52.05,92 52.05,89.1 v1(57.45,83.7) ; v1(77.55,42.9) FPGA1S.D7@78.05,42.4
  Bottom Layer w0.2: v1(57.45,83.7) 57.45,77.6 57.15,77.3 57.15,74.5 75.35,56.3 75.35,51.5 76.15,50.7 76.15,47.2 77.55,45.8 v1(77.55,42.9)
RED2: FPGA1S.D6 R109.1 | length 63.8
  Top Layer w0.2: R109.1@48.35,94.05 48.35,92.9 49.55,91.7 49.55,87 v1(52.35,84.2) ; v1(76.55,42.9) FPGA1S.D6@77.05,42.4
  MidLayer1 w0.127: 76.05,43.4 76.05,44.4
  MidLayer1 w0.2: v1(52.35,84.2) 52.35,83.7 52.05,83.4 52.05,82.6 54.825,79.775 54.825,74.775 69.246,60.395 ; 69.25,60.4 69.55,60.1 69.55,60.092 ; 69.546,60.096 69.55,60.092 ; 76.05,43.4 v1(76.55,42.9) ; 76.05,44.4 76.05,46.3 75.25,47.1 75.25,48.1 73.45,49.9 73.45,52 72.35,53.1 72.35,56.1 69.55,58.9 69.55,60.092
RED#: J5.1 R101.2 R102.2 R109.2 | length 19.7
  Top Layer w0.4: R109.2@48.35,95.95 48.35,97 48.75,97.4 50.95,97.4 ; R102.2@50.95,95.95 50.95,97.4 ; R101.2@53.55,95.95 53.55,97.4 ; J5.1@62.484,100.965 59.915,100.965 58.15,99.2 55.35,99.2 53.55,97.4 ; 50.95,97.4 53.55,97.4
RS232_CTS: FPGA1S.F2 R91.1 | length 83.6
  Top Layer w0.2: v1(70.95,41.3) 71.25,41.3 71.65,40.9 72.55,40.9 FPGA1S.F2@73.05,40.4
  Top Layer w0.3: R91.1@25.275,99.375 25.275,98.475 v3(25.95,97.8)
  MidLayer1 w0.2: v3(25.95,97.8) 30.35,93.4 36.85,93.4 44.55,85.7 44.55,81.8 46.801,79.549 46.801,65.149 69.572,42.378 69.572,42.078 70.35,41.3 v1(70.95,41.3)
RS232_RTS: FPGA1S.E1 LED5.2 U4.10 | length 87.9
  Top Layer w0.2: v1(70.45,42.1) 71.35,42.1 FPGA1S.E1@72.05,41.4
  Top Layer w0.3: U4.10@21.175,99.375 21.175,98.375 21.55,98 23.15,98 25.15,96 v3(31.15,96) 31.15,96.2 LED5.2@31.15,97.45
  MidLayer1 w0.2: v3@31.15,95.8 v3(31.15,96) 33.25,93.9 37.05,93.9 44.95,86 44.95,82.2 47.201,79.949 47.201,65.349 v1(70.45,42.1)
RS232_RX: FPGA1S.A5 R90.1 | length 76.2
  Top Layer w0.2: v1(72.65,52) 75.05,52 75.35,51.7 75.35,47.1 76.05,46.4 FPGA1S.A5@76.05,45.4
  Top Layer w0.3: R90.1@34.35,99.35 v3(34.35,100.8)
  MidLayer1 w0.2: v3(34.35,100.8) 34.35,98.5 48.25,84.6 49.35,84.6 52.15,81.8 ; 52.152,81.802 54.399,79.576 54.399,74.576 69.052,59.902 ; 69.05,59.9 69.05,58.8 71.95,55.9 71.95,52.7 v1(72.65,52)
RS232_TX: FPGA1S.F7 LED4.2 U4.11 | length 100
  Top Layer w0.3: U4.11@20.525,99.375 20.525,98.025 21.15,97.4 22.95,97.4 25.15,95.2 32.15,95.2 33.35,96.4 39.95,96.4 40.35,96 v1(41.05,96) 41.05,97.2 41.045,97.198 40.489,96.988 LED4.2@40.95,97.45 ; v1(77.55,40.9) FPGA1S.F7@78.05,40.4
  MidLayer1 w0.2: v1(41.05,96) 41.05,93.1 48.25,85.9 52.15,85.9 54.55,83.5 54.55,82.1 57.35,79.3 57.35,74.6 73.25,58.7 73.25,53.5 74.25,52.5 74.25,50.3 76.05,48.5 76.05,47.5 77.75,45.8 77.75,43.7 78.35,43.1 78.35,41.7 v1(77.55,40.9)
RTS: J4.8 U4.7 | length 26.4
  Top Layer w0.3: v3(20.95,96) 20.95,95.425 21.175,95.2 U4.7@21.175,93.825 ; v3(28.55,110) 28.55,108.8 28.69,108.66 J4.8@28.69,106.855
  Bottom Layer w0.3: v3(20.95,96) 20.95,101 20.15,101.8 20.15,107 23.15,110 v3(28.55,110)
RX: J4.3 U4.13 | length 11.7
  Top Layer w0.3: U4.13@19.225,99.375 19.225,102.275 19.55,102.6 25.95,102.6 27.305,103.955 J4.3@27.305,104.015
SOFT_TCK: FPGA1S.F21 U1S.18 | length 90.7
  Top Layer w0.2: FPGA1S.F21@92.05,40.4 92.55,40.9 94.55,40.9 95.55,41.9 98.25,41.9 99.85,43.5 106.65,43.5 106.85,43.3 108.85,43.3 v1(109.45,43.9)
  Top Layer w0.4: v3(156.95,71.2) 157.325,70.825 U1S.18@159.425,70.825
  Bottom Layer w0.2: v1(109.45,43.9) 109.45,46.5 111.45,48.5 114.85,48.5 117.45,51.1 117.45,53.3 121.25,57.1 130.75,57.1 131.85,56 150.35,56 153.45,59.1 153.45,61.1 158.65,66.3 158.65,69.6 157.05,71.2 v3(156.95,71.2)
SOFT_TDI: FPGA1S.E22 U1S.16 | length 82.4
  Top Layer w0.2: FPGA1S.E22@93.05,41.4 94.45,41.4 95.35,42.3 98.05,42.3 98.65,42.9 99.65,43.9 v1(107.85,43.9)
  Top Layer w0.4: v3(157.35,69.2) 157.675,69.525 U1S.16@159.425,69.525
  Bottom Layer w0.2: v1(107.85,43.9) 107.85,45.5 112.45,50.1 120.65,58.3 131.35,58.3 132.45,57.2 142.35,57.2 149.65,64.5 154.35,64.5 155.75,65.9 157.15,65.9 158.15,66.9 158.15,68.5 157.45,69.2 v3(157.35,69.2)
SOFT_TDO: FPGA1S.D22 U1S.8 | length 71.5
  Top Layer w0.2: FPGA1S.D22@93.05,42.4 93.95,42.4 v1(94.45,42.9)
  Top Layer w0.4: v3(147.85,65) 150.55,65 151.05,65.5 151.05,67 151.625,67.575 U1S.8@152.875,67.575
  Bottom Layer w0.2: v1(94.45,42.9) 94.95,42.4 96.35,42.4 97.75,43.8 100.95,43.8 102.15,45 106.05,45 121.35,60.3 143.15,60.3 v3(147.85,65)
SOFT_TMS: FPGA1S.E21 U1S.14 | length 78.5
  Top Layer w0.2: FPGA1S.E21@92.05,41.4 92.55,41.9 94.35,41.9 95.15,42.7 96.95,42.7 97.45,43.2 v1(98.05,43.2)
  Top Layer w0.4: v3(157.35,67.9) 157.675,68.225 U1S.14@159.425,68.225
  Bottom Layer w0.2: v1(98.05,43.2) 101.35,43.2 102.75,44.6 106.35,44.6 121.65,59.9 143.95,59.9 150.95,66.9 156.45,66.9 157.35,67.8 v3(157.35,67.9)
SPKR_L: J6.5 J6.5A J6.5B LS2.1 | length 44.4
  MidLayer1 w0.6: J6.5A@24.85,16.95 24.9,16.95 30.55,22.6 30.55,47.8 29.21,49.14 LS2.1@29.21,58.42
SPKR_R: J6.3 J6.3A J6.3B LS1.1 | length 152.1
  MidLayer1 w0.6: J6.3B@23.75,11.3 23.85,11.2 24.05,11 24.4,11 J6.3A@24.85,11 ; J6.3A@24.85,11.3 28.55,15 28.55,17.7 31.75,20.9 v3(31.75,52.9)
  MidLayer2 w0.5: v3(31.75,52.9) 46.75,52.9 49.85,56 71.55,56 74.85,59.3 92.85,59.3 95.95,56.2 117.95,56.2 120.17,58.42 LS1.1@133.35,58.42
SRAM0_A0: FPGA1S.L6 U5.5 | length 27
  Top Layer w0.2: U5.5@52.21,39.49 61.24,39.49 v1(61.25,39.5) ; v1(76.55,34.9) FPGA1S.L6@77.05,35.4
  MidLayer2 w0.127: 73.05,35.4 76.05,35.4
  MidLayer2 w0.2: v1(61.25,39.5) 65.65,39.5 69.75,35.4 73.05,35.4 ; 76.05,35.4 v1(76.55,34.9)
SRAM0_A1: FPGA1S.K4 U5.4 | length 24.9
  Top Layer w0.2: U5.4@52.21,40.29 53.84,40.29 53.85,40.3 v1(61.75,40.3) ; v1(74.55,35.9) FPGA1S.K4@75.05,36.4
  MidLayer1 w0.2: v1(61.75,40.3) 62.45,40.3 66.25,36.5 69.35,36.5 69.95,35.9 v1(74.55,35.9)
SRAM0_A2: FPGA1S.H5 U5.3 | length 25.9
  Top Layer w0.2: U5.3@52.21,41.09 61.24,41.09 v1(61.25,41.1) ; v1(75.55,37.9) FPGA1S.H5@76.05,38.4
  MidLayer1 w0.2: v1(61.25,41.1) 62.35,41.1 66.15,37.3 73.95,37.3 74.55,37.9 v1(75.55,37.9)
SRAM0_A3: FPGA1S.G6 U5.2 | length 26.3
  Top Layer w0.2: U5.2@52.21,41.89 61.74,41.89 v1(61.75,41.9) ; v1(75.55,38.9) 76.55,38.9 FPGA1S.G6@77.05,39.4
  MidLayer1 w0.2: v1(61.75,41.9) 62.35,41.9 64.673,39.577 65.35,38.9 v1(75.55,38.9)
SRAM0_A4: FPGA1S.F3 U5.1 | length 24.2
  Top Layer w0.2: U5.1@52.21,42.69 61.04,42.69 61.65,43.3 64.184,43.3 65.084,42.4 65.15,42.4 69.05,42.4 70.35,41.1 70.35,40.4 70.95,39.8 71.65,39.8 71.75,39.9 73.55,39.9 FPGA1S.F3@74.05,40.4
SRAM0_A5: FPGA1S.G1 U5.44 | length 10.5
  Top Layer w0.2: U5.44@63.36,42.69 64.16,42.69 64.85,42 68.85,42 69.95,40.9 69.95,40.2 70.45,39.7 70.75,39.4 FPGA1S.G1@72.05,39.4
SRAM0_A6: FPGA1S.G2 U5.43 | length 11.5
  Top Layer w0.2: U5.43@63.36,41.89 64.36,41.89 64.65,41.6 68.65,41.6 69.55,40.7 69.55,40 70.387,39.163 70.65,38.9 72.55,38.9 FPGA1S.G2@73.05,39.4
SRAM0_A7: FPGA1S.K3 U5.42 | length 14
  Top Layer w0.2: U5.42@63.36,41.09 64.74,41.09 64.85,41.2 66.65,41.2 66.75,41.1 66.75,39.6 67.45,38.9 70.05,38.9 71.05,37.9 72.35,37.9 72.55,37.7 72.55,37 72.65,36.9 73.55,36.9 FPGA1S.K3@74.05,36.4
SRAM0_A8: FPGA1S.T2 U5.27 | length 10.6
  Top Layer w0.2: U5.27@63.36,29.09 67.94,29.09 69.75,30.9 72.55,30.9 FPGA1S.T2@73.05,30.4
SRAM0_A9: FPGA1S.T1 U5.26 | length 9.6
  Top Layer w0.2: U5.26@63.36,28.29 64.34,28.29 64.65,28.6 68.05,28.6 69.85,30.4 FPGA1S.T1@72.05,30.4
SRAM0_A10: FPGA1S.U2 U5.25 | length 10.9
  Top Layer w0.2: U5.25@63.36,27.49 64.24,27.49 64.95,28.2 68.25,28.2 69.95,29.9 72.55,29.9 FPGA1S.U2@73.05,29.4
SRAM0_A11: FPGA1S.V3 U5.24 | length 12.1
  Top Layer w0.2: U5.24@63.36,26.69 64.86,26.69 65.25,26.3 68.35,26.3 70.95,28.9 73.55,28.9 FPGA1S.V3@74.05,28.4
SRAM0_A12: FPGA1S.V1 U5.23 | length 9.7
  Top Layer w0.2: U5.23@63.36,25.89 68.54,25.89 71.05,28.4 FPGA1S.V1@72.05,28.4
SRAM0_A13: FPGA1S.W1 U5.22 | length 21.3
  Top Layer w0.2: U5.22@52.21,25.89 53.46,25.89 54.45,24.9 68.75,24.9 71.25,27.4 FPGA1S.W1@72.05,27.4
SRAM0_A14: FPGA1S.V2 U5.21 | length 22.7
  Top Layer w0.2: U5.21@52.21,26.69 53.56,26.69 54.95,25.3 68.55,25.3 71.15,27.9 72.55,27.9 FPGA1S.V2@73.05,28.4
SRAM0_A15: FPGA1S.V5 U5.20 | length 25.6
  Top Layer w0.2: U5.20@52.21,27.49 53.16,27.49 53.17,27.5 53.65,27.5 55.15,26 v1(61.65,26) ; v1(75.55,27.9) FPGA1S.V5@76.05,28.4
  MidLayer1 w0.127: 74.05,27.4 75.05,27.4 75.25,27.6
  MidLayer1 w0.2: v1(61.65,26) 70.05,26 71.65,27.6 73.85,27.6 74.05,27.4 ; 75.25,27.6 v1(75.55,27.9)
SRAM0_A16: FPGA1S.V4 U5.19 | length 24.4
  Top Layer w0.2: U5.19@52.21,28.29 53.75,28.29 55.44,26.6 v1(60.65,26.6) ; v1(74.55,27.9) FPGA1S.V4@75.05,28.4
  MidLayer1 w0.2: v1(60.65,26.6) 62.55,26.6 ; 62.55,26.7 62.65,26.6 69.95,26.6 71.35,28 74.15,28 74.25,27.9 v1(74.55,27.9)
SRAM0_A17: FPGA1S.U5 U5.18 | length 26.2
  Top Layer w0.2: U5.18@52.21,29.09 53.85,29.09 55.74,27.2 v1(61.65,27.2) ; v1(75.55,28.9) FPGA1S.U5@76.05,29.4
  MidLayer1 w0.127: 74.05,28.4 75.05,28.4
  MidLayer1 w0.2: v1(61.65,27.2) 62.65,28.2 66.15,28.2 66.95,27.4 69.95,27.4 70.95,28.4 74.05,28.4 ; 75.05,28.4 v1(75.55,28.9)
SRAM0_A18: FPGA1S.U6 U5.28 | length 14.4
  Top Layer w0.2: U5.28@63.36,29.89 64.76,29.89 v1(64.95,29.7) ; v1(75.55,29.9) 76.55,29.9 FPGA1S.U6@77.05,29.4
  MidLayer1 w0.127: 74.05,29.4 75.05,29.4
  MidLayer1 w0.2: v1(64.95,29.7) 65.25,29.4 73.05,29.4 73.15,29.3 73.85,29.3 73.95,29.4 74.05,29.4 ; 75.05,29.4 v1(75.55,29.9)
SRAM0_D0: FPGA1S.L4 U5.7 | length 24.3
  Top Layer w0.2: U5.7@52.21,37.89 61.24,37.89 v1(61.25,37.9) ; v1(74.55,34.9) FPGA1S.L4@75.05,35.4
  MidLayer1 w0.127: 73.05,35.4 74.05,35.4
  MidLayer1 w0.2: v1(61.25,37.9) 64.15,37.9 65.95,36.1 69.15,36.1 69.85,35.4 73.05,35.4 ; 74.05,35.4 v1(74.55,34.9)
SRAM0_D1: FPGA1S.L3 U5.8 | length 23
  Top Layer w0.2: U5.8@52.21,37.09 61.74,37.09 v1(61.75,37.1) ; v1(73.55,34.9) FPGA1S.L3@74.05,35.4
  MidLayer1 w0.2: v1(61.75,37.1) 64.25,37.1 65.65,35.7 68.85,35.7 69.65,34.9 v1(73.55,34.9)
SRAM0_D2: FPGA1S.M5 U5.9 | length 25.5
  Top Layer w0.2: U5.9@52.21,36.29 61.24,36.29 v1(61.25,36.3) ; v1(75.55,33.9) FPGA1S.M5@76.05,34.4
  MidLayer2 w0.127: 73.05,33.4 75.05,33.4
  MidLayer2 w0.2: v1(61.25,36.3) 67.65,36.3 70.55,33.4 73.05,33.4 ; 75.05,33.4 v1(75.55,33.9)
SRAM0_D3: FPGA1S.M4 U5.10 | length 23.7
  Top Layer w0.2: U5.10@52.21,35.49 59.64,35.49 v1(59.65,35.5) ; v1(74.55,33.9) FPGA1S.M4@75.05,34.4
  MidLayer1 w0.127: 73.05,34.4 74.05,34.4
  MidLayer1 w0.2: v1(59.65,35.5) 64.55,35.5 64.75,35.3 68.65,35.3 69.55,34.4 73.05,34.4 ; 74.05,34.4 v1(74.55,33.9)
SRAM0_D4: FPGA1S.M3 U5.13 | length 22.8
  Top Layer w0.2: U5.13@52.21,33.09 53.06,33.09 53.25,32.9 58.65,32.9 v1(59.05,33.3) ; v1(73.55,33.9) FPGA1S.M3@74.05,34.4
  MidLayer1 w0.2: v1(59.05,33.3) 61.55,33.3 61.65,33.2 62.45,33.2 62.55,33.3 65.85,33.3 66.05,33.1 67.95,33.1 68.75,33.9 v1(73.55,33.9)
SRAM0_D5: FPGA1S.N4 U5.14 | length 24
  Top Layer w0.2: U5.14@52.21,32.29 59.44,32.29 v1(59.65,32.5) ; v1(74.55,32.9) FPGA1S.N4@75.05,33.4
  MidLayer1 w0.127: 73.05,33.4 74.05,33.4
  MidLayer1 w0.2: v1(59.65,32.5) 60.05,32.9 61.15,32.9 61.25,32.8 63.25,32.8 63.35,32.9 65.65,32.9 65.85,32.7 71.75,32.7 71.95,32.9 72.45,33.4 73.05,33.4 ; 74.05,33.4 v1(74.55,32.9)
SRAM0_D6: FPGA1S.N3 U5.15 | length 22.8
  Top Layer w0.2: U5.15@52.21,31.49 59.94,31.49 v1(59.95,31.5) ; v1(73.55,32.9) FPGA1S.N3@74.05,33.4
  MidLayer1 w0.2: v1(59.95,31.5) 60.75,32.3 63.65,32.3 63.85,32.5 65.35,32.5 65.55,32.3 71.95,32.3 72.55,32.9 v1(73.55,32.9)
SRAM0_D7: FPGA1S.T5 U5.16 | length 24.3
  Top Layer w0.2: U5.16@52.21,30.69 60.64,30.69 v1(60.65,30.7) ; v1(75.55,30.9) FPGA1S.T5@76.05,30.4
  MidLayer1 w0.2: v1(60.65,30.7) 64.75,30.7 65.15,31.1 66.75,31.1 66.95,30.9 v1(75.55,30.9)
SRAM0_D8: FPGA1S.T4 U5.29 | length 12.3
  Top Layer w0.2: U5.29@63.36,30.69 65.76,30.69 v1(65.95,30.5) ; v1(74.55,29.9) FPGA1S.T4@75.05,30.4
  MidLayer1 w0.127: 73.05,30.4 74.05,30.4
  MidLayer1 w0.2: v1(65.95,30.5) 66.55,30.5 66.75,30.3 72.95,30.3 73.05,30.4 ; 74.05,30.4 v1(74.55,29.9)
SRAM0_D9: FPGA1S.T6 U5.30 | length 15.2
  Top Layer w0.2: U5.30@63.36,31.49 64.54,31.49 64.55,31.5 v1(64.65,31.5) ; v1(76.55,31.9) 76.55,30.9 FPGA1S.T6@77.05,30.4
  MidLayer1 w0.2: v1(64.65,31.5) 67.05,31.5 67.25,31.3 74.95,31.3 75.55,31.9 v1(76.55,31.9)
SRAM0_D10: FPGA1S.M6 U5.31 | length 19
  Top Layer w0.2: v1(61.75,31.7) 62.34,32.29 U5.31@63.36,32.29 ; v1(76.55,32.9) 76.55,33.9 FPGA1S.M6@77.05,34.4
  MidLayer1 w0.127: 72.95,32.4 75.05,32.4
  MidLayer1 w0.2: v1(61.75,31.7) 63.85,31.7 64.25,32.1 65.15,32.1 65.35,31.9 72.45,31.9 72.95,32.4 ; 75.05,32.4 75.15,32.5 76.15,32.5 v1(76.55,32.9)
SRAM0_D11: FPGA1S.N2 U5.32 | length 10.6
  Top Layer w0.2: U5.32@63.36,33.09 63.96,33.09 64.95,32.1 70.85,32.1 71.65,32.9 72.55,32.9 FPGA1S.N2@73.05,33.4
SRAM0_D12: FPGA1S.N1 U5.35 | length 9.9
  Top Layer w0.2: U5.35@63.36,35.49 64.14,35.49 64.55,35.9 68.684,35.9 71.184,33.4 FPGA1S.N1@72.05,33.4
SRAM0_D13: FPGA1S.M2 U5.36 | length 11.1
  Top Layer w0.2: U5.36@63.36,36.29 64.34,36.29 64.55,36.5 68.65,36.5 71.25,33.9 72.55,33.9 FPGA1S.M2@73.05,34.4
SRAM0_D14: FPGA1S.M1 U5.37 | length 9.8
  Top Layer w0.2: U5.37@63.36,37.09 64.46,37.09 64.65,36.9 68.85,36.9 71.35,34.4 FPGA1S.M1@72.05,34.4
SRAM0_D15: FPGA1S.L2 U5.38 | length 11.1
  Top Layer w0.2: U5.38@63.36,37.89 64.36,37.89 64.95,37.3 69.05,37.3 71.45,34.9 72.55,34.9 FPGA1S.L2@73.05,35.4
SRAM0_E: FPGA1S.L5 U5.6 | length 26
  Top Layer w0.2: U5.6@52.21,38.69 61.74,38.69 v1(61.75,38.7) ; v1(75.55,34.9) FPGA1S.L5@76.05,35.4
  MidLayer2 w0.127: 73.05,34.4 75.05,34.4
  MidLayer2 w0.2: v1(61.75,38.7) 65.85,38.7 70.15,34.4 73.05,34.4 ; 75.05,34.4 v1(75.55,34.9)
SRAM0_LB: FPGA1S.L1 U5.39 | length 10.1
  Top Layer w0.2: U5.39@63.36,38.69 64.16,38.69 65.15,37.7 69.25,37.7 71.55,35.4 FPGA1S.L1@72.05,35.4
SRAM0_OE: FPGA1S.K1 U5.41 | length 10.4
  Top Layer w0.2: U5.41@63.36,40.29 63.96,40.29 65.75,38.5 69.85,38.5 ; FPGA1S.K1@72.05,36.4 71.663,36.787 71.563,36.787 69.915,38.435 ; 69.85,38.5 69.915,38.435 ; 69.85,38.5 69.915,38.435
SRAM0_UB: FPGA1S.K2 U5.40 | length 11.4
  Top Layer w0.2: U5.40@63.36,39.49 64.06,39.49 65.45,38.1 69.45,38.1 71.65,35.9 72.55,35.9 FPGA1S.K2@73.05,36.4
SRAM0_WE: FPGA1S.U4 U5.17 | length 24.1
  Top Layer w0.2: U5.17@52.21,29.89 53.86,29.89 55.65,28.1 v1(60.65,28.1) ; v1(74.55,28.9) FPGA1S.U4@75.05,29.4
  MidLayer1 w0.2: v1(60.65,28.1) 61.45,28.9 v1(74.55,28.9)
SRAM1_A0: FPGA1S.K21 U6.5 | length 11.5
  Top Layer w0.2: FPGA1S.K21@92.05,36.4 92.55,35.9 94.55,35.9 94.75,36.1 94.75,36.7 96.25,38.2 99.45,38.2 100.65,39.4 U6.5@101.575,39.4
SRAM1_A1: FPGA1S.K22 U6.4 | length 10.1
  Top Layer w0.2: FPGA1S.K22@93.05,36.4 93.85,36.4 96.05,38.6 99.15,38.6 100.75,40.2 U6.4@101.575,40.2
SRAM1_A2: FPGA1S.K20 U6.3 | length 12.4
  Top Layer w0.2: FPGA1S.K20@91.05,36.4 91.55,36.9 93.75,36.9 95.85,39 98.75,39 100.75,41 U6.3@101.575,41
SRAM1_A3: FPGA1S.G21 U6.2 | length 10.9
  Top Layer w0.2: FPGA1S.G21@92.05,39.4 92.55,38.9 95.15,38.9 95.65,39.4 98.55,39.4 100.95,41.8 U6.2@101.55,41.8
SRAM1_A4: FPGA1S.G22 U6.1 | length 10.1
  Top Layer w0.2: FPGA1S.G22@93.05,39.4 94.95,39.4 95.35,39.8 98.35,39.8 99.35,40.8 99.35,41.2 100.75,42.6 U6.1@101.575,42.6
SRAM1_A5: FPGA1S.M17 U6.44 | length 28.7
  Top Layer w0.2: FPGA1S.M17@88.05,34.4 v1(88.55,34.9) ; v1(103.75,39.4) 104.85,40.5 108.55,40.5 110.65,42.6 U6.44@112.725,42.6
  MidLayer1 w0.127: 89.05,35.4 89.05,36.4 ; 90.05,37.4 91.05,37.4
  MidLayer1 w0.2: v1(88.55,34.9) 89.05,35.4 ; 89.05,36.4 90.05,37.4 ; 91.05,37.4 100.45,37.4 101.55,38.5 102.45,39.4 v1(103.75,39.4)
SRAM1_A6: FPGA1S.L18 U6.43 | length 26.5
  Top Layer w0.2: FPGA1S.L18@89.05,35.4 v1(89.55,35.9) ; v1(103.15,38.7) 103.95,38.7 105.15,39.9 108.75,39.9 110.65,41.8 U6.43@112.725,41.8
  MidLayer1 w0.127: 90.05,36.4 91.05,36.4
  MidLayer1 w0.2: v1(89.55,35.9) 90.05,36.4 ; 91.05,36.4 96.45,36.4 96.65,36.2 99.95,36.2 102.45,38.7 v1(103.15,38.7)
SRAM1_A7: FPGA1S.K19 U6.42 | length 25.1
  Top Layer w0.2: FPGA1S.K19@90.05,36.4 v1(90.55,35.9) ; v1(103.95,38.1) 107.75,38.1 110.65,41 ; 110.65,41 U6.42@112.725,41
  MidLayer1 w0.2: v1(90.55,35.9) 92.35,35.9 92.45,35.8 100.15,35.8 102.45,38.1 v1(103.95,38.1)
SRAM1_A8: FPGA1S.V19 U6.27 | length 24.7
  Top Layer w0.2: FPGA1S.V19@90.05,28.4 v1(90.55,27.9) ; v1(104.05,26.9) 108.75,26.9 110.85,29 U6.27@112.725,29
  MidLayer1 w0.127: 91.05,27.4 92.05,27.4
  MidLayer1 w0.2: v1(90.55,27.9) 91.05,27.4 ; 92.05,27.4 93.05,27.4 94.15,26.3 101.35,26.3 101.95,26.9 v1(104.05,26.9)
SRAM1_A9: FPGA1S.W20 U6.26 | length 23.2
  Top Layer w0.2: FPGA1S.W20@91.05,27.4 v1(91.55,26.9) ; v1(103.35,26.3) 108.95,26.3 110.85,28.2 U6.26@112.725,28.2
  MidLayer1 w0.2: v1(91.55,26.9) 92.85,26.9 93.85,25.9 101.65,25.9 102.05,26.3 v1(103.35,26.3)
SRAM1_A10: FPGA1S.W19 U6.25 | length 24.2
  Top Layer w0.2: FPGA1S.W19@90.05,27.4 v1(90.55,26.9) ; v1(104.05,25.7) 109.15,25.7 110.85,27.4 U6.25@112.725,27.4
  MidLayer1 w0.127: 91.05,26.4 92.05,26.4
  MidLayer1 w0.2: v1(90.55,26.9) 91.05,26.4 ; 92.05,26.4 92.75,26.4 93.65,25.5 101.95,25.5 102.15,25.7 v1(104.05,25.7)
SRAM1_A11: FPGA1S.Y20 U6.24 | length 22.9
  Top Layer w0.2: FPGA1S.Y20@91.05,26.4 v1(91.55,25.9) ; v1(103.35,25.1) 109.35,25.1 110.85,26.6 U6.24@112.725,26.6 U6.24@112.75,26.6
  MidLayer1 w0.2: v1(91.55,25.9) 92.55,25.9 93.35,25.1 v1(103.35,25.1)
SRAM1_A12: FPGA1S.Y21 U6.23 | length 22
  Top Layer w0.2: FPGA1S.Y21@92.05,26.4 92.55,25.9 93.35,25.9 94.75,24.5 109.55,24.5 110.85,25.8 U6.23@112.725,25.8 U6.23@112.75,25.8
SRAM1_A13: FPGA1S.Y22 U6.22 | length 9.5
  Top Layer w0.2: FPGA1S.Y22@93.05,26.4 93.65,26.4 95.15,24.9 99.75,24.9 100.65,25.8 U6.22@101.575,25.8
SRAM1_A14: FPGA1S.W21 U6.21 | length 10.9
  Top Layer w0.2: FPGA1S.W21@92.05,27.4 92.55,26.9 93.75,26.9 95.35,25.3 99.25,25.3 100.55,26.6 U6.21@101.575,26.6
SRAM1_A15: FPGA1S.W22 U6.20 | length 9.9
  Top Layer w0.2: FPGA1S.W22@93.05,27.4 93.85,27.4 95.15,26.1 95.55,25.7 98.95,25.7 100.65,27.4 U6.20@101.575,27.4
SRAM1_A16: FPGA1S.V21 U6.19 | length 11.3
  Top Layer w0.2: FPGA1S.V21@92.05,28.4 92.55,27.9 93.95,27.9 95.203,26.647 95.75,26.1 98.65,26.1 100.75,28.2 U6.19@101.575,28.2
SRAM1_A17: FPGA1S.V22 U6.18 | length 10.5
  Top Layer w0.2: FPGA1S.V22@93.05,28.4 94.05,28.4 95.95,26.5 98.45,26.5 99.75,27.8 99.75,28.1 100.65,29 U6.18@101.575,29
SRAM1_A18: FPGA1S.V20 U6.28 | length 23.7
  Top Layer w0.2: FPGA1S.V20@91.05,28.4 v1(91.55,27.9) ; v1(103.05,27.5) 108.55,27.5 110.85,29.8 U6.28@112.725,29.8 U6.28@112.75,29.8
  MidLayer1 w0.2: v1(91.55,27.9) 93.25,27.9 94.45,26.7 101.05,26.7 101.85,27.5 v1(103.05,27.5)
SRAM1_D0: FPGA1S.L21 U6.7 | length 11.5
  Top Layer w0.2: FPGA1S.L21@92.05,35.4 92.55,34.9 95.15,34.9 95.55,35.3 95.55,36.3 96.65,37.4 100.15,37.4 100.55,37.8 U6.7@101.575,37.8
SRAM1_D1: FPGA1S.M22 U6.8 | length 10.4
  Top Layer w0.2: FPGA1S.M22@93.05,34.4 99.45,34.4 99.65,34.6 99.65,35.6 100.15,36.1 100.15,36.4 100.75,37 U6.8@101.575,37
SRAM1_D2: FPGA1S.M21 U6.9 | length 11.6
  Top Layer w0.2: FPGA1S.M21@92.05,34.4 92.55,33.9 99.85,33.9 100.05,34.1 100.05,35.4 100.55,35.9 100.55,36.1 100.65,36.2 101.55,36.2 U6.9@101.575,36.2
SRAM1_D3: FPGA1S.N22 U6.10 | length 10.1
  Top Layer w0.2: FPGA1S.N22@93.05,33.4 99.95,33.4 100.45,33.9 100.45,35.2 100.65,35.4 U6.10@101.575,35.4
SRAM1_D4: FPGA1S.N21 U6.13 | length 9.8
  Top Layer w0.2: FPGA1S.N21@92.05,33.4 92.55,32.9 94.25,32.9 94.35,33 99.65,33 U6.13@101.575,33
SRAM1_D5: FPGA1S.U20 U6.14 | length 12.5
  Top Layer w0.2: FPGA1S.U20@91.05,29.4 91.55,29.9 91.55,30.7 91.75,30.9 93.65,30.9 95.35,32.6 99.35,32.6 99.75,32.2 U6.14@101.575,32.2
SRAM1_D6: FPGA1S.T22 U6.15 | length 9.6
  Top Layer w0.2: FPGA1S.T22@93.05,30.4 93.85,30.4 95.65,32.2 98.95,32.2 99.75,31.4 U6.15@101.575,31.4
SRAM1_D7: FPGA1S.T21 U6.16 | length 10.4
  Top Layer w0.2: FPGA1S.T21@92.05,30.4 92.55,29.9 94.05,29.9 94.15,30 95.35,30 95.75,29.6 99.85,29.6 100.85,30.6 U6.16@101.575,30.6
SRAM1_D8: FPGA1S.V18 U6.29 | length 26.1
  Top Layer w0.2: FPGA1S.V18@89.05,28.4 v1(89.55,27.9) ; v1(103.75,28.1) 108.25,28.1 110.75,30.6 U6.29@112.725,30.6
  MidLayer1 w0.127: 90.05,28.4 92.05,28.4
  MidLayer1 w0.2: v1(89.55,27.9) 90.05,28.4 ; 92.05,28.4 93.45,28.4 94.75,27.1 100.75,27.1 101.75,28.1 v1(103.75,28.1)
SRAM1_D9: FPGA1S.U19 U6.30 | length 25.1
  Top Layer w0.2: FPGA1S.U19@90.05,29.4 v1(90.55,28.9) ; v1(104.45,28.7) 108.05,28.7 110.75,31.4 U6.30@112.725,31.4
  MidLayer1 w0.2: v1(90.55,28.9) 93.55,28.9 94.95,27.5 100.55,27.5 101.75,28.7 v1(104.45,28.7)
SRAM1_D10: FPGA1S.U18 U6.31 | length 25.8
  Top Layer w0.2: FPGA1S.U18@89.05,29.4 v1(89.55,28.9) ; v1(103.75,29.3) 107.85,29.3 110.75,32.2 U6.31@112.725,32.2
  MidLayer1 w0.127: 90.05,29.4 91.05,29.4
  MidLayer1 w0.2: v1(89.55,28.9) 90.05,29.4 ; 91.05,29.4 93.75,29.4 94.45,28.7 100.75,28.7 101.15,29.1 103.45,29.1 v1(103.75,29.3)
SRAM1_D11: FPGA1S.T18 U6.32 | length 25.3
  Top Layer w0.2: FPGA1S.T18@89.05,30.4 v1(89.55,29.9) ; v1(102.95,29.8) 103.35,30 107.65,30 110.65,33 U6.32@112.725,33
  MidLayer1 w0.2: v1(89.55,29.9) 92.95,29.9 93.05,30 95.55,30 95.75,29.8 v1(102.95,29.8)
SRAM1_D12: FPGA1S.R18 U6.35 | length 25.7
  Top Layer w0.2: FPGA1S.R18@89.05,31.4 v1(89.55,31.9) ; v1(103.35,32.1) 107.55,32.1 110.95,35.5 111.45,35.5 111.55,35.4 U6.35@112.725,35.4
  MidLayer1 w0.2: v1(89.55,31.9) 89.95,32.3 90.15,32.5 102.05,32.5 102.45,32.1 v1(103.35,32.1)
SRAM1_D13: FPGA1S.T17 U6.36 | length 27.8
  Top Layer w0.2: FPGA1S.T17@88.05,30.4 88.55,30.9 v1(88.55,31.9) ; v1(105.05,32.7) 107.25,32.7 110.75,36.2 U6.36@112.725,36.2
  MidLayer1 w0.2: v1(88.55,31.9) 89.55,32.9 102.35,32.9 102.55,32.7 v1(105.05,32.7)
SRAM1_D14: FPGA1S.M18 U6.37 | length 25.7
  Top Layer w0.2: FPGA1S.M18@89.05,34.4 v1(89.55,33.9) ; v1(105.05,33.8) 107.55,33.8 110.75,37 U6.37@112.725,37
  MidLayer1 w0.2: v1(89.55,33.9) 90.15,33.3 102.55,33.3 102.65,33.2 104.45,33.2 v1(105.05,33.8)
SRAM1_D15: FPGA1S.M20 U6.38 | length 23.5
  Top Layer w0.2: FPGA1S.M20@91.05,34.4 v1(91.55,33.9) ; v1(105.15,35.4) 108.35,35.4 110.75,37.8 U6.38@112.725,37.8
  MidLayer1 w0.2: v1(91.55,33.9) 101.05,33.9 102.55,35.4 v1(105.15,35.4)
SRAM1_E: FPGA1S.L22 U6.6 | length 10.3
  Top Layer w0.2: FPGA1S.L22@93.05,35.4 94.75,35.4 95.15,35.8 95.15,36.5 96.45,37.8 99.85,37.8 100.65,38.6 U6.6@101.575,38.6
SRAM1_LB: FPGA1S.M19 U6.39 | length 24.8
  Top Layer w0.2: FPGA1S.M19@90.05,34.4 v1(90.55,33.9) ; v1(103.05,36.2) 108.25,36.2 110.65,38.6 U6.39@112.725,38.6
  MidLayer1 w0.127: 91.05,34.4 92.05,34.4
  MidLayer1 w0.2: v1(90.55,33.9) 91.05,34.4 ; 92.05,34.4 100.85,34.4 102.65,36.2 v1(103.05,36.2)
SRAM1_OE: FPGA1S.L19 U6.41 | length 25.2
  Top Layer w0.2: FPGA1S.L19@90.05,35.4 v1(90.55,34.9) ; v1(103.05,37.5) 107.95,37.5 110.65,40.2 U6.41@112.725,40.2
  MidLayer1 w0.2: v1(90.55,34.9) 91.15,35.5 92.15,35.5 92.25,35.4 100.45,35.4 102.55,37.5 v1(103.05,37.5)
SRAM1_UB: FPGA1S.L20 U6.40 | length 23.7
  Top Layer w0.2: FPGA1S.L20@91.05,35.4 v1(91.55,34.9) ; v1(103.75,36.9) 108.15,36.9 110.65,39.4 U6.40@112.725,39.4
  MidLayer1 w0.2: v1(91.55,34.9) 100.65,34.9 102.65,36.9 v1(103.75,36.9)
SRAM1_WE: FPGA1S.U21 U6.17 | length 10.2
  Top Layer w0.2: FPGA1S.U21@92.05,29.4 92.55,28.9 94.35,28.9 94.45,28.8 95.35,28.8 95.75,29.2 100.05,29.2 100.65,29.8 U6.17@101.575,29.8
SW_DIP0: FPGA1S.Y6 R11.1 S1.1 | length 47
  Top Layer w0.2: v1(76.55,25.9) FPGA1S.Y6@77.05,26.4
  MidLayer1 w0.2: S1.1@49.53,4 52.53,7 68.85,7 71.75,9.9 71.75,19.3 76.55,24.1 v1(76.55,25.9)
  Bottom Layer w0.3: R11.1@46.55,2.45 47.98,2.45 S1.1@49.53,4
SW_DIP1: FPGA1S.V6 R12.1 S1.2 | length 49.5
  Top Layer w0.2: v1(76.55,27.9) FPGA1S.V6@77.05,28.4
  MidLayer1 w0.2: S1.2@52.07,4 54.67,6.6 69.05,6.6 72.15,9.7 72.15,19.1 76.832,23.782 77.15,24.1 77.15,27.3 v1(76.55,27.9)
  Bottom Layer w0.3: R12.1@48.26,7.305 48.26,6.19 48.65,5.8 50.27,5.8 S1.2@52.07,4
SW_DIP2: FPGA1S.U7 R13.1 S1.3 | length 48.3
  Top Layer w0.2: v1(77.55,29.9) FPGA1S.U7@78.05,29.4
  MidLayer1 w0.2: S1.3@54.61,4 56.81,6.2 69.25,6.2 72.55,9.5 72.55,16.9 77.95,22.3 77.95,27.3 78.35,27.7 78.35,29.1 v1(77.55,29.9)
  Bottom Layer w0.3: R13.1@52.07,6.67 52.07,5.68 52.25,5.5 53.11,5.5 S1.3@54.61,4
SW_DIP3: FPGA1S.AA4 R14.1 S1.4 | length 37.4
  Top Layer w0.2: S1.4@57.15,4 61.95,8.8 70.05,8.8 71.05,9.8 71.05,15 74.55,18.5 74.55,24.9 FPGA1S.AA4@75.05,25.4
  Bottom Layer w0.3: R14.1@55.88,7.305 55.88,5.27 S1.4@57.15,4
SW_DIP4: FPGA1S.AB4 R15.1 S1.5 | length 33.1
  Top Layer w0.2: S1.5@59.69,4 63.89,8.2 70.15,8.2 71.55,9.6 71.55,14.9 75.05,18.4 FPGA1S.AB4@75.05,24.4
  Bottom Layer w0.3: S1.5@59.69,4 R15.1@59.69,6.67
